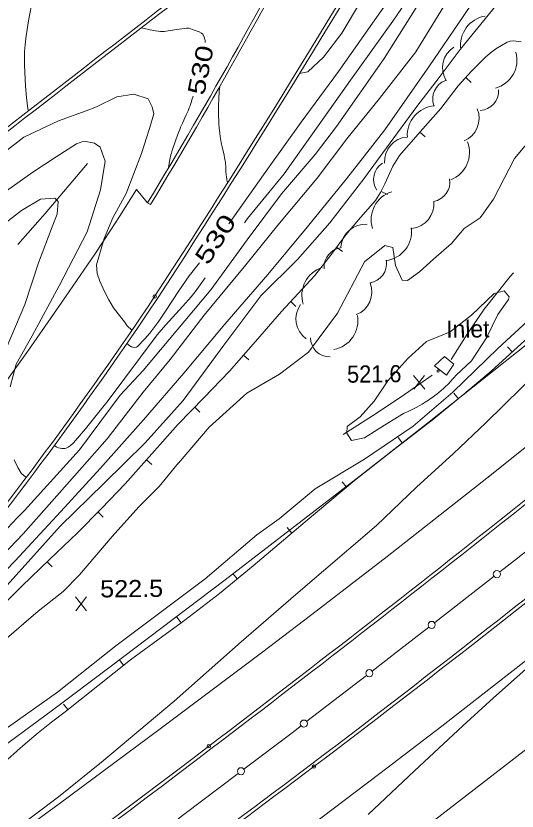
# Model space of a CAD drawing. Extents: x 2361284 to 2366480, y 6976556 to 6985346.
# Drawn here: x 2364043.9 to 2364184.5, y 6978961.5 to 6979184.4 of the extents above; entities that cross this region are included whole.
import ezdxf
from ezdxf.enums import TextEntityAlignment as Align

# ---------------------------------------------------------------- set-up
doc = ezdxf.new("R2010")
doc.units = 0
doc.header["$LTSCALE"] = 1.9
doc.header["$PDMODE"] = 32
doc.header["$PDSIZE"] = 0.95
for name, color, linetype, lineweight in [('12', 7, 'Continuous', 13), ('13', 7, 'Continuous', 13), ('14', 7, 'Continuous', 13), ('16', 7, 'Continuous', 13), ('21', 7, 'Continuous', 13), ('27', 7, 'Continuous', 13), ('3', 7, 'Continuous', 13), ('5', 7, 'Continuous', 13), ('8', 7, 'Continuous', 13)]:
    doc.layers.add(name, color=color, linetype=linetype, lineweight=lineweight)

msp = doc.modelspace()

# ---------------------------------------------------------------- linework, layer by layer
at = {"layer": '12'}
for p, q in [((2364158.582, 6979079.718), (2364155.465, 6979083.569)), ((2364155.502, 6979079.689), (2364158.545, 6979083.598)), ((2364063.758, 6979017.633), (2364060.641, 6979021.484)), ((2364060.678, 6979017.604), (2364063.721, 6979021.513))]:
    msp.add_line(p, q, dxfattribs=at)
for points in [[(2364270.047, 6979355.871), (2364267.179, 6979352.433), (2364263.514, 6979348.788), (2364259.134, 6979342.526), (2364252.821, 6979334.246), (2364244.434, 6979324.426), (2364237.45, 6979316.449), (2364226.159, 6979303.861), (2364216.776, 6979289.47), (2364207.276, 6979275.71), (2364193.581, 6979258.298), (2364182.659, 6979243.604), (2364173.302, 6979227.584), (2364164.063, 6979213.665), (2364152.683, 6979194.795), (2364143.92, 6979182.292), (2364134.428, 6979168.781), (2364123.904, 6979154.58), (2364114.942, 6979142.034), (2364103.663, 6979126.066)], [(2364190.468, 6979203.916), (2364183.285, 6979193.607), (2364177.567, 6979186.023), (2364168.553, 6979174.905), (2364162.656, 6979167.049), (2364156.393, 6979158.939), (2364147.873, 6979147.387), (2364141.514, 6979138.727), (2364131.942, 6979126.315), (2364122.91, 6979116.109), (2364112.616, 6979105.87), (2364102.246, 6979092.06), (2364090.823, 6979076.532), (2364080.125, 6979064.709), (2364068.584, 6979053.268), (2364056.366, 6979041.342), (2364048.122, 6979032.173), (2364037.168, 6979020.088), (2364026.593, 6979008.847), (2364017.561, 6978999.58), (2364006.88, 6978989.089), (2363996.257, 6978978.796), (2363986.291, 6978968.891)], [(2364097.008, 6979176.905), (2364097.018, 6979176.965), (2364097.024, 6979177.452), (2364096.755, 6979178.423), (2364096.338, 6979179.248), (2364095.994, 6979179.546), (2364095.302, 6979179.878), (2364093.877, 6979180.346), (2364092.474, 6979180.874), (2364091.761, 6979180.926), (2364088.386, 6979180.413), (2364085.51, 6979179.976), (2364084.491, 6979179.947), (2364082.447, 6979180.287), (2364079.1, 6979181.015)], [(2364103.333, 6979137.664), (2364103.319, 6979137.652), (2364103.291, 6979137.666), (2364103.262, 6979137.726), (2364103.2, 6979137.961), (2364103.103, 6979138.506), (2364102.979, 6979139.339), (2364102.924, 6979139.69), (2364102.863, 6979140.126), (2364102.834, 6979140.417), (2364102.8, 6979140.999), (2364102.782, 6979141.581), (2364102.759, 6979142.356), (2364102.74, 6979142.743), (2364102.687, 6979143.32), (2364102.646, 6979143.607), (2364102.541, 6979144.192), (2364102.462, 6979144.58), (2364102.286, 6979145.354), (2364101.717, 6979147.668), (2364101.55, 6979148.445), (2364101.476, 6979148.836), (2364101.282, 6979149.993), (2364101.196, 6979150.572), (2364101.081, 6979151.442), (2364100.987, 6979152.315), (2364100.949, 6979152.752), (2364100.843, 6979154.302), (2364100.803, 6979155.079), (2364100.759, 6979156.246), (2364100.737, 6979157.413), (2364100.734, 6979157.997), (2364100.743, 6979159.165), (2364100.756, 6979159.749), (2364100.786, 6979160.625), (2364100.845, 6979161.791), (2364100.883, 6979162.374), (2364100.951, 6979163.247), (2364101.077, 6979164.554)], [(2364086.713, 6979141.756), (2364086.899, 6979143.008), (2364087.011, 6979143.63), (2364087.207, 6979144.561), (2364087.405, 6979145.368), (2364087.548, 6979145.902), (2364087.858, 6979146.963), (2364088.022, 6979147.49), (2364088.37, 6979148.538), (2364088.737, 6979149.58), (2364089.509, 6979151.653), (2364089.863, 6979152.54), (2364090.113, 6979153.126), (2364090.633, 6979154.287), (2364091.696, 6979156.6), (2364092.203, 6979157.765), (2364092.521, 6979158.551), (2364092.671, 6979158.947), (2364092.884, 6979159.546), (2364093.135, 6979160.317), (2364093.292, 6979160.834), (2364093.592, 6979161.873)], [(2364095.406, 6979115.176), (2364092.521, 6979111.509), (2364089.591, 6979107.334), (2364085.899, 6979101.606), (2364084.002, 6979098.758), (2364081.478, 6979095.42), (2364080.112, 6979093.851), (2364077.978, 6979091.699), (2364077.714, 6979091.528), (2364077.063, 6979091.443), (2364076.335, 6979091.636), (2364075.857, 6979091.88), (2364075.06, 6979092.542)], [(2364190.718, 6979085.091), (2364175.717, 6979070.308), (2364166.628, 6979061.711), (2364156.238, 6979052.223), (2364145.07, 6979041.545), (2364122.392, 6979022.179), (2364107.067, 6979008.902), (2364088.274, 6978992.313), (2364067.966, 6978975.228), (2364055.897, 6978965.434), (2364034.171, 6978949.225)]]:
    msp.add_lwpolyline(points, dxfattribs=at)
at = {"layer": '13'}
for points in [[(2364260.253, 6979358.468), (2364258.587, 6979355.902), (2364254.156, 6979351.609), (2364249.053, 6979345.62), (2364244.465, 6979339.057), (2364239.747, 6979332.521), (2364232.312, 6979323.59), (2364226.574, 6979317.065), (2364219.819, 6979310.11), (2364214.638, 6979302.881), (2364209.739, 6979295.314), (2364202.59, 6979285.795), (2364197.141, 6979275.094), (2364190.091, 6979263.515), (2364182.824, 6979252.576), (2364176.89, 6979245.709), (2364167.979, 6979232.093), (2364163.432, 6979225.369), (2364151.094, 6979204.162), (2364144.48, 6979194.997), (2364135.296, 6979179.539), (2364130.19, 6979172.791), (2364125.789, 6979168.708), (2364123.494, 6979168.207)], [(2364279.344, 6979353.179), (2364277.252, 6979351.189), (2364274.247, 6979347.45), (2364268.021, 6979340.711), (2364262.133, 6979333.134), (2364256.769, 6979326.253), (2364246.945, 6979314.969), (2364239.61, 6979305.899), (2364229.176, 6979292.659), (2364215.801, 6979277.371), (2364201.331, 6979257.282), (2364193.547, 6979247.187), (2364181.89, 6979229.836), (2364170.046, 6979212.442), (2364158.511, 6979196.001), (2364149.596, 6979182.866), (2364137.762, 6979166.292), (2364119.16, 6979140.094), (2364108.879, 6979127.596), (2364108.02, 6979126.388)], [(2364197.315, 6979244.173), (2364183.849, 6979226.844), (2364171.528, 6979211.176), (2364160.593, 6979193.702), (2364147.216, 6979172.392), (2364133.845, 6979153.374), (2364127.879, 6979145.537), (2364118.374, 6979134.486), (2364108.736, 6979121.594), (2364098.578, 6979107.547), (2364079.613, 6979084.965), (2364073.127, 6979078.074), (2364061.714, 6979062.683), (2364046.354, 6979045.687), (2364044.382, 6979043.758), (2364038.62, 6979037.743), (2364037.308, 6979036.86), (2364035.156, 6979036.04), (2364033.781, 6979036.447)], [(2364185.61, 6979216.16), (2364173.185, 6979202.041), (2364165.333, 6979189.426), (2364156.037, 6979174.326), (2364145.922, 6979161.181), (2364136.698, 6979149.861), (2364128.372, 6979138.872), (2364117.418, 6979125.667), (2364108.402, 6979114.59), (2364096.746, 6979100.469), (2364087.194, 6979088.017), (2364079.64, 6979078.936), (2364069.474, 6979065.837), (2364056.106, 6979050.721), (2364045.925, 6979039.212), (2364033.004, 6979025.608), (2364027.234, 6979020.324), (2364017.521, 6979009.051), (2364013.502, 6979005.823), (2364011.774, 6979006.616), (2364010.641, 6979007.975)], [(2364189.082, 6979211.893), (2364177.312, 6979196.03), (2364169.355, 6979184.164), (2364159.924, 6979170.383), (2364147.366, 6979152.393), (2364136.655, 6979138.68), (2364125.633, 6979125.135), (2364114.559, 6979111.828), (2364102.55, 6979097.984), (2364091.03, 6979084.223), (2364079.744, 6979071.156), (2364067.563, 6979057.509), (2364056.498, 6979045.433), (2364043.737, 6979031.661), (2364033.309, 6979020.922), (2364024.286, 6979011.645), (2364016.209, 6979002.907), (2364004.416, 6978990.565), (2363995.725, 6978982.211), (2363989.197, 6978976.569), (2363986.279, 6978974.371), (2363982.605, 6978972.676), (2363981.377, 6978972.455), (2363980.041, 6978973.092)], [(2364047.488, 6979157.764), (2364047.419, 6979157.77), (2364047.263, 6979158.312), (2364046.853, 6979161.469), (2364046.652, 6979164.677), (2364046.336, 6979170.563), (2364046.323, 6979174.379), (2364046.472, 6979176.285), (2364046.785, 6979178.726), (2364047.563, 6979183.576), (2364048.533, 6979188.806), (2364048.678, 6979190.738), (2364048.706, 6979193.332), (2364048.808, 6979194.628), (2364049.607, 6979201.214), (2364049.911, 6979202.584), (2364050.07, 6979202.84)], [(2364374.42, 6979177.413), (2364371.437, 6979173.564), (2364366.886, 6979168.361), (2364360.579, 6979161.601), (2364353.982, 6979154.957), (2364341.554, 6979140.949), (2364332.732, 6979131.734), (2364325.931, 6979124.399), (2364320.317, 6979118.526), (2364312.96, 6979111.774), (2364304.036, 6979102.7), (2364292.967, 6979092.024), (2364266.46, 6979069.42), (2364249.398, 6979054.798), (2364237.122, 6979043.94), (2364227.83, 6979036.592), (2364213.456, 6979024.384), (2364191.149, 6979005.012), (2364177.88, 6978993.245), (2364169.265, 6978985.383), (2364155.723, 6978972.782), (2364142.669, 6978960.479)], [(2364076.425, 6979096.226), (2364075.122, 6979097.494), (2364074.392, 6979098.577), (2364072.581, 6979100.84), (2364071.295, 6979102.517), (2364069.943, 6979104.755), (2364068.65, 6979107.262), (2364067.444, 6979110), (2364066.734, 6979112.163), (2364066.54, 6979114.612), (2364068.701, 6979121.954), (2364071.144, 6979127.767), (2364074.86, 6979134.593), (2364079.154, 6979145.804), (2364081.388, 6979152.766), (2364082.559, 6979156.927), (2364082.14, 6979158.853), (2364081.039, 6979161.064), (2364076.945, 6979162.425), (2364072.202, 6979161.7), (2364066.499, 6979158.894), (2364063.59, 6979157.707), (2364055.875, 6979154.983), (2364046.099, 6979150.35), (2364040.759, 6979146.169)], [(2364191.328, 6979153.461), (2364183.702, 6979144.398), (2364177.812, 6979132.951), (2364174.131, 6979127.756), (2364169.6, 6979124.723), (2364166.048, 6979120.599), (2364161.06, 6979116.141), (2364157.094, 6979112.583), (2364153.771, 6979110.144), (2364152.227, 6979110.266), (2364150.368, 6979114.349), (2364149.669, 6979119.443), (2364147.381, 6979119.974), (2364141.716, 6979115.408), (2364134.063, 6979100.994), (2364125.976, 6979090.076), (2364117.885, 6979083.908), (2364108.675, 6979078.612), (2364098.154, 6979069.05), (2364089.49, 6979059.027)], [(2364042.274, 6979080.38), (2364044.003, 6979086.726), (2364048.478, 6979094.67), (2364056.025, 6979108.712), (2364063.922, 6979123.848), (2364067.611, 6979135.574), (2364068.915, 6979143.597), (2364067.518, 6979147.513), (2364066.003, 6979148.652), (2364062.931, 6979149.2), (2364060.888, 6979148.53), (2364055.201, 6979144.886), (2364048.652, 6979140.554), (2364038.331, 6979133.295)], [(2364041.223, 6979091.12), (2364046.455, 6979103.441), (2364050.283, 6979115.157), (2364054.078, 6979125.255), (2364055.494, 6979128.788), (2364055.791, 6979132.291), (2364054.792, 6979133.232), (2364050.814, 6979133.004), (2364045.474, 6979129.813), (2364040.094, 6979125.642)], [(2364096.996, 6979110.961), (2364094.194, 6979107.035), (2364093.085, 6979105.635), (2364090.73, 6979102.948), (2364085.856, 6979097.708), (2364083.558, 6979094.974), (2364069.762, 6979076.582), (2364063.397, 6979068.64), (2364060.024, 6979064.727), (2364059.135, 6979063.86), (2364058.606, 6979063.474), (2364058.018, 6979063.196), (2364057.606, 6979063.103), (2364056.79, 6979063.097), (2364055.83, 6979063.315), (2364055.358, 6979063.505), (2364054.671, 6979063.907)], [(2364167.38, 6979083.669), (2364171.683, 6979087.64), (2364175.911, 6979094.122), (2364179.099, 6979100.632), (2364182.108, 6979104.901), (2364182.241, 6979105.592), (2364180.856, 6979107.299), (2364178.063, 6979106.543), (2364171.661, 6979100.462), (2364165.674, 6979095.784), (2364159.059, 6979093.1), (2364153.934, 6979088.391), (2364151.36, 6979085.657), (2364148.194, 6979082.087), (2364144.428, 6979076.362), (2364140.419, 6979072.023), (2364136.804, 6979069.298), (2364136.753, 6979067.357), (2364138.052, 6979065.349), (2364141.675, 6979066.114), (2364147.312, 6979069.658), (2364152.632, 6979072.899)], [(2364111.482, 6979038.916), (2364117.73, 6979043.345), (2364127.851, 6979051.753), (2364141.672, 6979060.104), (2364155.344, 6979069.394), (2364166.495, 6979078.881), (2364179.06, 6979091.11), (2364188.566, 6979099.912)], [(2364152.632, 6979072.899), (2364153.017, 6979073.059), (2364153.776, 6979073.392), (2364154.524, 6979073.742), (2364155.017, 6979073.987), (2364155.996, 6979074.501), (2364157.224, 6979075.188), (2364157.829, 6979075.541), (2364158.725, 6979076.086), (2364159.607, 6979076.652), (2364160.043, 6979076.945), (2364160.903, 6979077.55), (2364161.328, 6979077.863), (2364161.959, 6979078.348), (2364162.621, 6979078.884), (2364163.052, 6979079.25), (2364163.893, 6979080), (2364164.303, 6979080.384), (2364165.105, 6979081.17), (2364165.883, 6979081.98), (2364166.391, 6979082.533), (2364166.724, 6979082.907), (2364167.38, 6979083.669)], [(2364089.51, 6979059.048), (2364084.102, 6979052.437), (2364078.436, 6979046.752), (2364070.874, 6979038.399), (2364061.787, 6979027.673), (2364057.151, 6979023.038), (2364050.191, 6979017.552), (2364039.996, 6979008.725), (2364028.747, 6978999.016), (2364019.212, 6978990.006), (2364007.762, 6978979.376), (2364002.047, 6978974.651), (2363984.79, 6978959.586)], [(2364046.825, 6979054.982), (2364045.364, 6979056.158), (2364044.428, 6979057.799), (2364043.388, 6979059.949)], [(2364000.434, 6978954.945), (2364017.903, 6978966.733), (2364030.157, 6978976.879), (2364055.538, 6978994.842), (2364071.935, 6979007.808), (2364096.969, 6979026.566), (2364111.482, 6979038.916)]]:
    msp.add_lwpolyline(points, dxfattribs=at)
at = {"layer": '14'}
for points in [[(2364420.159, 6979267.113), (2364400.723, 6979248.336), (2364390.885, 6979239.073), (2364367.462, 6979217.462), (2364355.655, 6979206.764), (2364337.799, 6979190.876), (2364315.598, 6979171.486), (2364300.731, 6979158.638), (2364270.855, 6979133.106), (2364244.209, 6979110.62), (2364230.829, 6979099.447), (2364210.669, 6979082.791), (2364189.937, 6979065.945), (2364176.031, 6979054.822), (2364148.013, 6979032.833), (2364126.906, 6979016.585), (2364112.779, 6979005.83), (2364084.388, 6978984.496), (2364056.021, 6978963.478), (2364041.79, 6978953.033), (2364020.372, 6978937.464), (2363990.222, 6978915.934), (2363975.045, 6978905.311), (2363972.005, 6978903.232)], [(2363951.494, 6978832.723), (2363965.118, 6978841.916), (2363992.242, 6978860.482), (2364021.619, 6978880.939), (2364036.247, 6978891.253), (2364058.115, 6978906.831), (2364078.805, 6978921.811), (2364092.528, 6978931.892), (2364119.847, 6978952.23), (2364146.002, 6978972.008), (2364163.349, 6978985.309), (2364197.851, 6979012.166), (2364222.356, 6979031.614), (2364234.536, 6979041.425), (2364252.715, 6979056.252), (2364279.783, 6979078.749), (2364309.686, 6979104.155), (2364329.473, 6979121.256), (2364342.603, 6979132.728), (2364368.725, 6979155.838), (2364391.388, 6979176.238), (2364402.645, 6979186.517), (2364419.438, 6979202.042)]]:
    msp.add_lwpolyline(points, dxfattribs=at)
at = {"layer": '16'}
for centre, radius, start, end in [((2364176.837, 6979176.218), 8.202, 98.96079, 188.96079), ((2364170.405, 6979169.842), 6.838, 122.31824, 212.31824), ((2364176.237, 6979172.015), 8.202, 285.10354, 15.10354), ((2364166.258, 6979161.093), 5.465, 110.15327, 200.15327), ((2364173.823, 6979163.306), 5.465, 272.94269, 2.94269), ((2364161.884, 6979150.941), 8.202, 94.18504, 184.18504), ((2364166.987, 6979155.655), 6.838, 292.5887, 22.5887), ((2364154.132, 6979143.578), 6.838, 94.18504, 184.18504), ((2364162.931, 6979146.091), 8.202, 290.83434, 20.83434), ((2364149.699, 6979138.512), 5.465, 122.79962, 212.79962), ((2364160.152, 6979137.738), 5.465, 279.618, 9.618), ((2364151.754, 6979127.246), 8.202, 107.32789, 197.32789), ((2364154.289, 6979131.61), 6.838, 275.76463, 5.76463), ((2364141.886, 6979119.144), 6.838, 85.62675, 175.62675), ((2364146.663, 6979123.899), 8.202, 277.28486, 7.28486), ((2364135.813, 6979113.964), 5.465, 95.75333, 185.75333), ((2364132.321, 6979106.051), 8.202, 107.90863, 197.90863), ((2364142.416, 6979114.967), 5.465, 278.319, 8.319), ((2364136.872, 6979106.981), 6.838, 291.51211, 21.51211), ((2364129.277, 6979099.425), 6.838, 144.2525, 234.2525), ((2364131.637, 6979098.934), 8.202, 280.34995, 10.34995), ((2364131.954, 6979094.243), 5.465, 180.99766, 270.99766)]:
    msp.add_arc(centre, radius, start, end, dxfattribs=at)
at = {"layer": '21'}
for points in [[(2364064.03, 6979142.98), (2364052.142, 6979128.996), (2364044.424, 6979120.273)], [(2364165.988, 6979088.016), (2364170.431, 6979095.19), (2364175.235, 6979102.146), (2364182.507, 6979111.354), (2364183.447, 6979112.363)], [(2364135.736, 6979066.997), (2364143.897, 6979072.246), (2364151.967, 6979077.623), (2364157.232, 6979081.233), (2364160.679, 6979083.665)]]:
    msp.add_lwpolyline(points, dxfattribs=at)
msp.add_circle((2364162.312, 6979084.817), 0.3, dxfattribs=at)
at = {"layer": '27'}
for p, q in [((2364170.067, 6979167.049), (2364171.56, 6979165.725)), ((2364157.211, 6979151.736), (2364158.714, 6979150.411)), ((2364146.32, 6979135.152), (2364148.118, 6979134.269)), ((2364133.866, 6979119.543), (2364135.478, 6979118.358)), ((2364120.991, 6979104.27), (2364122.454, 6979102.904)), ((2364183.138, 6979090.129), (2364181.794, 6979091.606)), ((2364107.773, 6979089.263), (2364109.276, 6979087.947)), ((2364168.013, 6979077.046), (2364166.757, 6979078.604)), ((2364094.071, 6979074.703), (2364095.504, 6979073.306)), ((2364152.34, 6979064.625), (2364151.115, 6979066.204)), ((2364080.561, 6979059.963), (2364082.053, 6979058.627)), ((2364136.657, 6979052.227), (2364135.382, 6979053.763)), ((2364066.969, 6979045.303), (2364068.383, 6979043.886)), ((2364121.298, 6979039.399), (2364120.003, 6979040.927)), ((2364052.661, 6979031.326), (2364054.044, 6979029.889)), ((2364105.979, 6979026.542), (2364104.725, 6979028.101)), ((2364090.246, 6979014.203), (2364089.081, 6979015.822)), ((2364074.127, 6979002.368), (2364072.882, 6979003.936)), ((2364058.486, 6978989.909), (2364057.241, 6978991.468))]:
    msp.add_line(p, q, dxfattribs=at)
for points in [[(2364185.621, 6979177.118), (2364183.549, 6979177.318), (2364182.56, 6979177.269), (2364181.653, 6979176.98), (2364178.481, 6979175.11), (2364176.992, 6979174.016), (2364175.593, 6979172.792), (2364171.66, 6979168.845), (2364167.99, 6979164.711), (2364165.548, 6979161.567), (2364163.128, 6979158.433), (2364157.31, 6979151.847), (2364151.524, 6979145.242), (2364149.623, 6979142.224), (2364147.389, 6979137.292), (2364146.192, 6979134.881), (2364144.723, 6979132.647), (2364140.568, 6979127.817), (2364136.414, 6979122.987), (2364132.139, 6979117.217), (2364127.742, 6979111.553), (2364123.101, 6979106.53), (2364118.427, 6979101.535), (2364111.147, 6979093.126), (2364103.826, 6979084.755), (2364096.636, 6979077.337), (2364089.426, 6979069.947), (2364081.995, 6979061.566), (2364074.544, 6979053.205), (2364067.94, 6979046.282), (2364061.194, 6979039.507), (2364053.384, 6979032.023), (2364045.585, 6979024.538), (2364038.294, 6979017.279)], [(2364021.719, 6978960.879), (2364028.056, 6978965.389), (2364034.354, 6978969.968), (2364038.046, 6978972.953), (2364041.647, 6978976.048), (2364045.861, 6978979.758), (2364050.126, 6978983.41), (2364053.918, 6978986.376), (2364057.741, 6978989.312), (2364066.892, 6978996.62), (2364076.052, 6979003.896), (2364083.681, 6979009.46), (2364091.329, 6979014.983), (2364100.988, 6979022.485), (2364110.475, 6979030.196), (2364117.737, 6979036.365), (2364124.999, 6979042.544), (2364131.933, 6979048.34), (2364138.919, 6979054.087), (2364149.74, 6979062.6), (2364160.609, 6979071.065), (2364168.976, 6979077.825), (2364177.21, 6979084.733), (2364188.72, 6979095.203)]]:
    msp.add_lwpolyline(points, dxfattribs=at)
at = {"layer": '3'}
for p, q in [((2364083.63, 6979105.173), (2364083.624, 6979105.163)), ((2364098.605, 6978978.91), (2364098.607, 6978978.912)), ((2364126.903, 6978974.701), (2364126.901, 6978974.699))]:
    msp.add_line(p, q, dxfattribs=at)
for points in [[(2364420.49, 6979297.498), (2364404.923, 6979282.861), (2364373.594, 6979253.799), (2364346.336, 6979228.833), (2364332.644, 6979216.423), (2364312.02, 6979197.901), (2364280.872, 6979170.343), (2364270.685, 6979161.47), (2364250.157, 6979143.91), (2364229.44, 6979126.579), (2364215.532, 6979115.14), (2364187.506, 6979092.511), (2364159.353, 6979070.211), (2364140.495, 6979055.466), (2364127.883, 6979045.688), (2364102.562, 6979026.249), (2364070.367, 6979001.877), (2364054.195, 6978989.794), (2364029.815, 6978971.825), (2364003.059, 6978952.52), (2363985.107, 6978939.817), (2363973.091, 6978931.414), (2363948.954, 6978914.753)], [(2363947.382, 6978968.611), (2363958.378, 6978980.037), (2363963.79, 6978985.815), (2363971.791, 6978994.586), (2363979.638, 6979003.504), (2363983.499, 6979008.027), (2363997.114, 6979024.394), (2364003.813, 6979032.652), (2364013.714, 6979045.153), (2364023.426, 6979057.811), (2364028.207, 6979064.205), (2364041.089, 6979081.826), (2364047.433, 6979090.697), (2364056.818, 6979104.093), (2364066.034, 6979117.611), (2364070.576, 6979124.422), (2364073.008, 6979128.156), (2364077.719, 6979135.72)], [(2364077.719, 6979135.72), (2364080.856, 6979131.99), (2364081.68, 6979131.497)], [(2364304.877, 6979071.097), (2364261.483, 6979036.532), (2364239.634, 6979019.443), (2364142.344, 6978944.234), (2364072.224, 6978890.134), (2364061.065, 6978881.712), (2364053.55, 6978876.2), (2364038.361, 6978865.392), (2364030.698, 6978860.082), (2364015.262, 6978849.617), (2363999.713, 6978839.314), (2363968.446, 6978818.974), (2363952.175, 6978808.479)]]:
    msp.add_lwpolyline(points, dxfattribs=at)
for centre, radius, start, end in [((2361717.634, 6980645.658), 2822.342, 326.93211, 330.04285), ((2361717.634, 6980645.658), 2823.302, 326.93211, 330.04285), ((2370974.71, 6970240.147), 11292.045, 127.31492, 127.90598), ((2370974.71, 6970240.147), 11291.085, 127.31492, 127.90598), ((2362844.81, 6979879.557), 1444.53, 328.83443, 332.83579), ((2362844.81, 6979879.557), 1445.49, 328.83443, 332.83579), ((2361757.968, 6982101.757), 3923.052, 307.14611, 311.3083), ((2361757.968, 6982101.757), 3924.012, 307.14611, 311.3083), ((2361158.91, 6982851.448), 4860.97, 307.20262, 309.88554), ((2361158.91, 6982851.448), 4861.93, 307.20262, 309.88554), ((2363164.208, 6979719.613), 1104.877, 315.19618, 326.24501), ((2363164.208, 6979719.613), 1105.837, 315.19618, 326.24501), ((2362288.408, 6981348.476), 2980.928, 303.88189, 307.37758), ((2362288.408, 6981348.476), 2981.888, 303.88189, 307.37758), ((2361607.754, 6982319.136), 4187.047, 304.02245, 306.98837), ((2361607.754, 6982319.136), 4188.007, 304.02245, 306.98837)]:
    msp.add_arc(centre, radius, start, end, dxfattribs=at)
for p in [(2364082.826, 6979105.697), (2364098.025, 6978979.674), (2364127.481, 6978973.934)]:
    msp.add_point(p, dxfattribs=at)
at = {"layer": '5'}
for p, q in [((2364161.368, 6979014.309), (2364178.027, 6979027.278)), ((2364125.521, 6978986.637), (2364142.248, 6978999.515))]:
    msp.add_line(p, q, dxfattribs=at)
for points in [[(2364179.595, 6979028.503), (2364183.783, 6979031.753), (2364195.397, 6979040.974)], [(2364143.827, 6979000.73), (2364151.512, 6979006.645), (2364159.75, 6979013.053)], [(2364107.836, 6978973.227), (2364121.38, 6978983.447), (2364123.893, 6978985.381)], [(2364089.378, 6978959.341), (2364091.026, 6978960.548), (2364106.248, 6978972.032)]]:
    msp.add_lwpolyline(points, dxfattribs=at)
for centre in [(2364178.808, 6979027.877), (2364160.527, 6979013.657), (2364143.034, 6979000.119), (2364124.681, 6978985.991), (2364107.048, 6978972.636)]:
    msp.add_circle(centre, 1, dxfattribs=at)
at = {"layer": '8'}
msp.add_lwpolyline([(2364166.77, 6979086.703), (2364164.139, 6979088.879), (2364161.344, 6979086.242), (2364164.649, 6979083.623)], close=True, dxfattribs=at)

# ---------------------------------------------------------------- texts
at = {"layer": '12'}
for rotation, width, p in [(78.616, 1.3, (2364098.063, 6979168.691)), (56.691, 1.4, (2364101.867, 6979120.456))]:
    msp.add_text(' 530 ', height=4.8, rotation=rotation, dxfattribs=dict(at, width=width)).set_placement(p, align=Align.CENTER)
for s, width, p in [('521.6', 0.95, (2364136.808, 6979081.539)), ('522.5', 1.1, (2364067.567, 6979021.357))]:
    msp.add_text(s, height=4.799, rotation=0.545, dxfattribs=dict(at, width=width)).set_placement(p)
at = {"layer": '8'}
msp.add_text('Inlet', height=4.799, rotation=0.545, dxfattribs=at).set_placement((2364164.619, 6979094.144))

doc.saveas('drawing.dxf')
